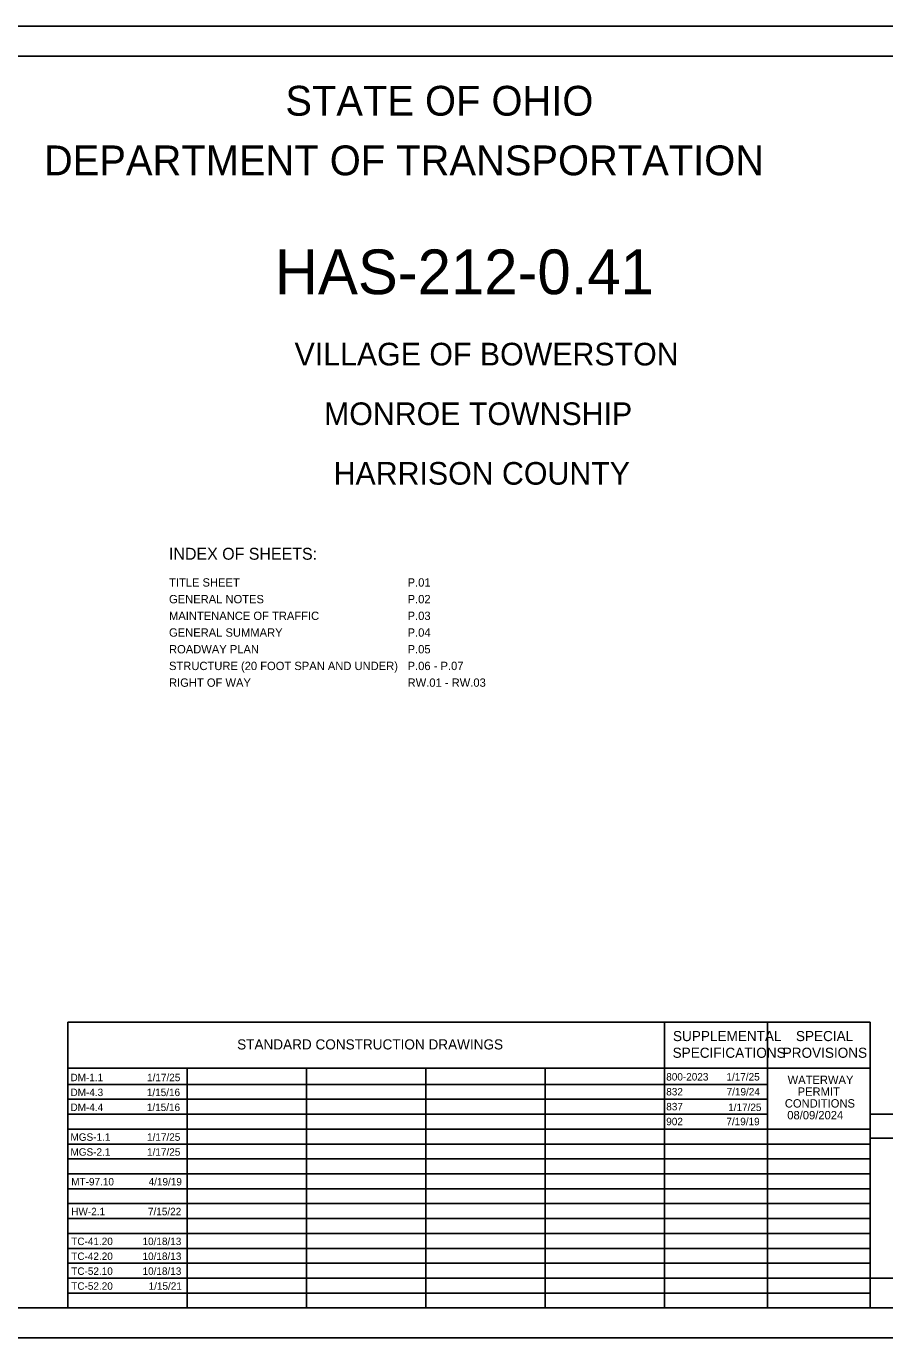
# Model space of a CAD drawing. Extents: x -19.9 to 41.9, y 0 to 32.3.
# Drawn here: x 9.45 to 23.84, y 0 to 22 of the extents above; entities that cross this region are included whole.
import ezdxf

# ---------------------------------------------------------------- set-up
doc = ezdxf.new("R2010")
doc.units = 0
for name, color, linetype in [('SH_Border', 7, 'Continuous'), ('SH_Cut_Line', 7, 'Continuous'), ('SH_Data', 7, 'Continuous'), ('SH_Text', 7, 'Continuous')]:
    doc.layers.add(name, color=color, linetype=linetype)

msp = doc.modelspace()

# ---------------------------------------------------------------- linework, layer by layer
at = {"layer": 'SH_Border'}
msp.add_lwpolyline([(1.5, 21.5), (33.5, 21.5), (33.5, 0.5), (1.5, 0.5)], close=True, dxfattribs=at)
at = {"layer": 'SH_Cut_Line'}
msp.add_lwpolyline([(0, 0), (34, 0), (34, 22), (0, 22)], close=True, dxfattribs=at)
at = {"layer": 'SH_Data'}
for p, q in [((10.15, 5.292), (23.6, 5.292)), ((10.15, 0.5), (10.15, 5.292)), ((20.15, 0.5), (20.15, 5.292)), ((21.875, 0.5), (21.875, 5.292)), ((23.6, 0.5), (23.6, 5.292)), ((10.15, 4.521), (23.6, 4.521)), ((12.15, 0.5), (12.15, 4.521)), ((14.15, 0.5), (14.15, 4.521)), ((16.15, 0.5), (16.15, 4.521)), ((18.15, 0.5), (18.15, 4.521)), ((10.15, 4.25), (21.875, 4.25)), ((10.15, 4), (21.875, 4)), ((10.15, 3.75), (21.875, 3.75)), ((23.6, 0.5), (23.6, 3.75)), ((23.6, 3.75), (26.4, 3.75)), ((10.15, 3.5), (23.6, 3.5)), ((23.6, 3.35), (26.4, 3.35)), ((10.15, 3.25), (23.6, 3.25)), ((10.15, 3), (23.6, 3)), ((10.15, 2.75), (23.6, 2.75)), ((10.15, 2.5), (23.6, 2.5)), ((10.15, 2.25), (23.6, 2.25)), ((10.15, 2), (23.6, 2)), ((10.15, 1.75), (23.6, 1.75)), ((10.15, 1.5), (23.6, 1.5)), ((10.15, 1.25), (23.6, 1.25)), ((10.15, 1), (23.6, 1)), ((10.15, 0.75), (23.6, 0.75)), ((23.6, 0.5), (26.4, 0.5))]:
    msp.add_line(p, q, dxfattribs=at)
msp.add_lwpolyline([(23.6, 0.5), (23.6, 1), (26.4, 1), (26.4, 0.5)], close=True, dxfattribs=at)

# ---------------------------------------------------------------- texts
at = {"layer": 'SH_Text'}
for s, height, p in [('STATE OF OHIO', 0.5, (13.795, 20.5)), ('DEPARTMENT OF TRANSPORTATION', 0.5, (9.747, 19.5)), ('HAS-212-0.41', 0.75, (13.617, 17.505)), ('VILLAGE OF BOWERSTON', 0.38, (13.949, 16.31)), ('MONROE TOWNSHIP', 0.38, (14.443, 15.31)), ('HARRISON COUNTY', 0.38, (14.603, 14.31)), ('INDEX OF SHEETS:', 0.2, (11.844, 13.051)), ('TITLE SHEET', 0.14, (11.844, 12.6)), ('P.01', 0.14, (15.844, 12.6)), ('GENERAL NOTES', 0.14, (11.844, 12.32)), ('P.02', 0.14, (15.844, 12.32)), ('MAINTENANCE OF TRAFFIC', 0.14, (11.844, 12.04)), ('P.03', 0.14, (15.844, 12.04)), ('GENERAL SUMMARY', 0.14, (11.844, 11.76)), ('P.04', 0.14, (15.844, 11.76)), ('ROADWAY PLAN', 0.14, (11.844, 11.48)), ('P.05', 0.14, (15.844, 11.48)), ('STRUCTURE (20 FOOT SPAN AND UNDER)', 0.14, (11.844, 11.2)), ('P.06 - P.07', 0.14, (15.844, 11.2)), ('RIGHT OF WAY', 0.14, (11.844, 10.92)), ('RW.01 - RW.03', 0.14, (15.844, 10.92)), ('SUPPLEMENTAL', 0.17, (20.293, 4.976)), ('SPECIAL', 0.17, (22.354, 4.976)), ('STANDARD CONSTRUCTION DRAWINGS', 0.17, (12.986, 4.836)), ('SPECIFICATIONS', 0.17, (20.287, 4.696)), ('PROVISIONS', 0.17, (22.132, 4.696)), ('DM-1.1', 0.125, (10.192, 4.304)), ('1/17/25', 0.125, (11.476, 4.304)), ('800-2023', 0.125, (20.18, 4.315)), ('1/17/25', 0.125, (21.189, 4.315)), ('DM-4.3', 0.125, (10.192, 4.054)), ('1/15/16', 0.125, (11.472, 4.054)), ('832', 0.125, (20.18, 4.065)), ('7/19/24', 0.125, (21.192, 4.065)), ('WATERWAY', 0.14, (22.215, 4.257)), ('PERMIT ', 0.14, (22.383, 4.059)), ('CONDITIONS', 0.14, (22.168, 3.862)), ('DM-4.4', 0.125, (10.192, 3.804)), ('1/15/16', 0.125, (11.472, 3.804)), ('837', 0.125, (20.18, 3.815)), ('1/17/25', 0.125, (21.218, 3.803)), ('08/09/2024', 0.14, (22.209, 3.664)), ('902', 0.125, (20.18, 3.565)), ('7/19/19', 0.125, (21.188, 3.565)), ('MGS-1.1', 0.125, (10.192, 3.304)), ('1/17/25', 0.125, (11.476, 3.304)), ('MGS-2.1', 0.125, (10.192, 3.054)), ('1/17/25', 0.125, (11.476, 3.054)), ('MT-97.10', 0.125, (10.205, 2.555)), ('4/19/19', 0.125, (11.502, 2.555)), ('HW-2.1', 0.125, (10.205, 2.055)), ('7/15/22', 0.125, (11.491, 2.055)), ('TC-41.20', 0.125, (10.205, 1.555)), ('10/18/13', 0.125, (11.4, 1.555)), ('TC-42.20', 0.125, (10.205, 1.305)), ('10/18/13', 0.125, (11.4, 1.305)), ('TC-52.10', 0.125, (10.205, 1.055)), ('10/18/13', 0.125, (11.4, 1.055)), ('TC-52.20', 0.125, (10.205, 0.805)), ('1/15/21', 0.125, (11.502, 0.805))]:
    msp.add_text(s, height=height, dxfattribs=at).set_placement(p)

doc.saveas('drawing.dxf')
